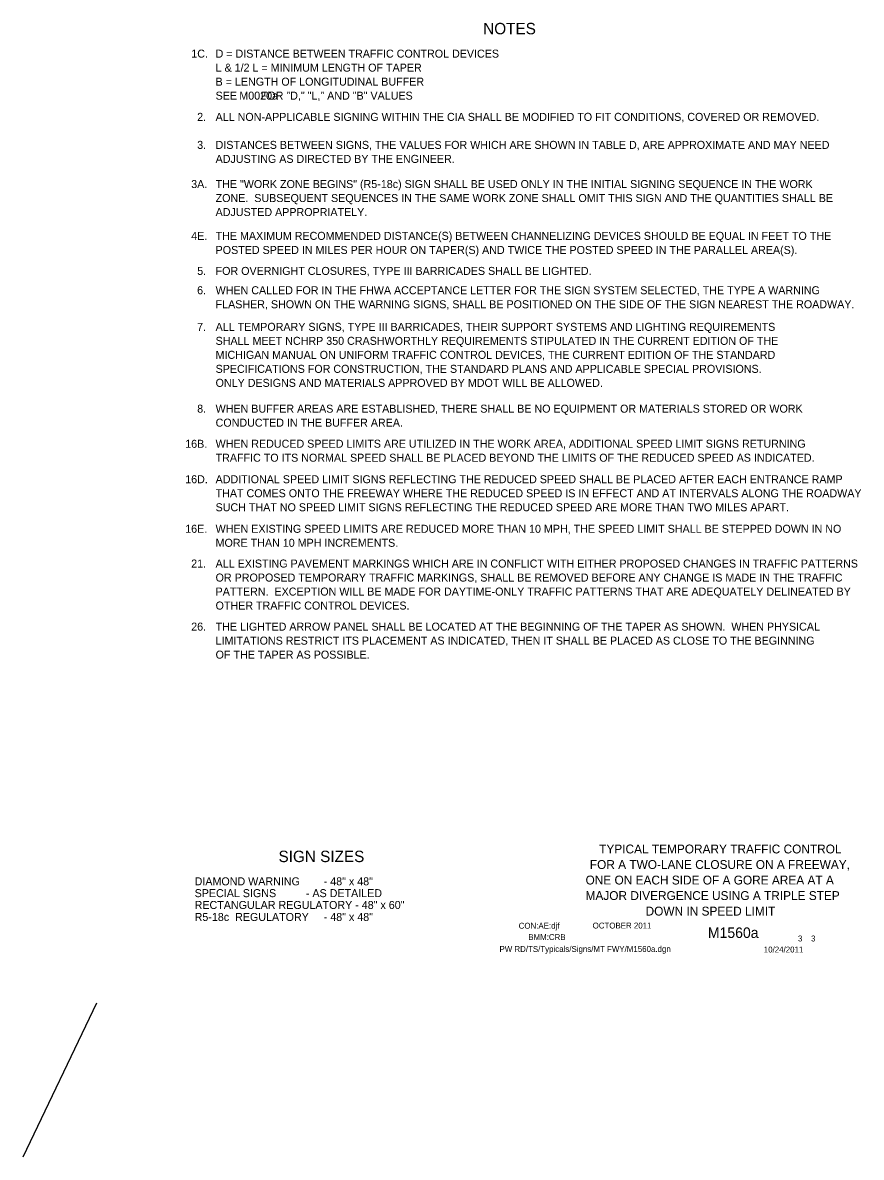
# Model space of a CAD drawing. Extents: x 16552 to 19508, y 5713 to 7079.
# Drawn here: x 18628 to 19508, y 5718 to 6909 of the extents above; entities that cross this region are included whole.
import ezdxf

# ---------------------------------------------------------------- set-up
doc = ezdxf.new("R2010")
doc.units = 0
for name, color, linetype in [('BORDER', 7, 'Continuous'), ('BORDER_SIGNAL_WO', 7, 'Continuous'), ('TYPICAL_TEXT_DIMEN_PR', 7, 'Continuous')]:
    doc.layers.add(name, color=color, linetype=linetype)

msp = doc.modelspace()

# ---------------------------------------------------------------- linework, layer by layer
at = {"layer": 'TYPICAL_TEXT_DIMEN_PR'}
msp.add_line((18705.8, 5880), (18628.3, 5718.1), dxfattribs=at)

# ---------------------------------------------------------------- texts
at = {"layer": 'BORDER'}
for s, p in [('TYPICAL TEMPORARY TRAFFIC CONTROL', (19233.2, 6037.1)), ('FOR A TWO-LANE CLOSURE ON A FREEWAY,', (19223.4, 6020.8)), ('ONE ON EACH SIDE OF A GORE AREA AT A ', (19218.9, 6004.5)), ('MAJOR DIVERGENCE USING A TRIPLE STEP ', (19218.9, 5988.2)), ('DOWN IN SPEED LIMIT', (19281.9, 5971.9))]:
    msp.add_text(s, height=9.3, dxfattribs=at).set_placement(p)
at = {"layer": 'BORDER_SIGNAL_WO'}
for s, height, p in [('CON:AE:djf  ', 6.2, (19148.7, 5958.1)), ('    OCTOBER 2011    ', 6.2, (19217.1, 5958.3)), ('    M1560a   ', 11, (19330.9, 5948.4)), ('BMM:CRB   ', 6.2, (19158.8, 5946.2)), (' 3    3 ', 6.2, (19439.4, 5944.7)), ('PW RD/TS/Typicals/Signs/MT FWY/M1560a.dgn      ', 6.2, (19128.6, 5933.7)), ('10/24/2011    ', 6.2, (19405.9, 5933.1))]:
    msp.add_text(s, height=height, dxfattribs=at).set_placement(p)
at = {"layer": 'TYPICAL_TEXT_DIMEN_PR'}
for s, height, p in [('NOTES', 12, (19111.5, 6897)), ('1C.', 8.4, (18805.2, 6872.5)), ('D = DISTANCE BETWEEN TRAFFIC CONTROL DEVICES', 8.4, (18830.7, 6872.5)), ('L & 1/2 L = MINIMUM LENGTH OF TAPER', 8.4, (18830.7, 6857.8)), ('B = LENGTH OF LONGITUDINAL BUFFER', 8.4, (18830.7, 6843.1)), ('SEE        FOR "D," "L," AND "B" VALUES', 8.4, (18830.7, 6828.4)), ('M0020a', 8.4, (18855.6, 6828.4)), ('2.', 8.4, (18811.4, 6806.1)), ('ALL NON-APPLICABLE SIGNING WITHIN THE CIA SHALL BE MODIFIED TO FIT CONDITIONS, COVERED OR REMOVED.', 8.4, (18830.7, 6806.1)), ('3.', 8.4, (18811.4, 6776.7)), ('DISTANCES BETWEEN SIGNS, THE VALUES FOR WHICH ARE SHOWN IN TABLE D, ARE APPROXIMATE AND MAY NEED', 8.4, (18830.7, 6776.7)), ('ADJUSTING AS DIRECTED BY THE ENGINEER.', 8.4, (18830.7, 6762)), ('3A.', 8.4, (18805.1, 6735.6)), ('THE "WORK ZONE BEGINS" (R5-18c) SIGN SHALL BE USED ONLY IN THE INITIAL SIGNING SEQUENCE IN THE WORK', 8.4, (18830.7, 6735.6)), ('ZONE.  SUBSEQUENT SEQUENCES IN THE SAME WORK ZONE SHALL OMIT THIS SIGN AND THE QUANTITIES SHALL BE', 8.4, (18830.7, 6720.9)), ('ADJUSTED APPROPRIATELY.', 8.4, (18830.7, 6706.2)), ('4E.', 8.4, (18805.1, 6681.2)), ('THE MAXIMUM RECOMMENDED DISTANCE(S) BETWEEN CHANNELIZING DEVICES SHOULD BE EQUAL IN FEET TO THE', 8.4, (18830.7, 6681.2)), ('POSTED SPEED IN MILES PER HOUR ON TAPER(S) AND TWICE THE POSTED SPEED IN THE PARALLEL AREA(S).', 8.4, (18830.7, 6666.4)), ('5.', 8.4, (18811.4, 6644.4)), ('FOR OVERNIGHT CLOSURES, TYPE III BARRICADES SHALL BE LIGHTED. ', 8.4, (18830.7, 6644.4)), ('6.', 8.4, (18811.3, 6624.1)), ('WHEN CALLED FOR IN THE FHWA ACCEPTANCE LETTER FOR THE SIGN SYSTEM SELECTED, THE TYPE A WARNING ', 8.4, (18830.7, 6624.1)), ('FLASHER, SHOWN ON THE WARNING SIGNS, SHALL BE POSITIONED ON THE SIDE OF THE SIGN NEAREST THE ROADWAY.', 8.4, (18830.7, 6609.4)), ('7.', 8.4, (18811.3, 6585.7)), ('ALL TEMPORARY SIGNS, TYPE III BARRICADES, THEIR SUPPORT SYSTEMS AND LIGHTING REQUIREMENTS', 8.4, (18830.7, 6585.7)), ('SHALL MEET NCHRP 350 CRASHWORTHLY REQUIREMENTS STIPULATED IN THE CURRENT EDITION OF THE', 8.4, (18830.7, 6571)), ('MICHIGAN MANUAL ON UNIFORM TRAFFIC CONTROL DEVICES, THE CURRENT EDITION OF THE STANDARD', 8.4, (18830.7, 6556.3)), ('SPECIFICATIONS FOR CONSTRUCTION, THE STANDARD PLANS AND APPLICABLE SPECIAL PROVISIONS.', 8.4, (18830.7, 6541.6)), ('ONLY DESIGNS AND MATERIALS APPROVED BY MDOT WILL BE ALLOWED.', 8.4, (18830.7, 6526.9)), ('8.', 8.4, (18811.4, 6499.8)), ('WHEN BUFFER AREAS ARE ESTABLISHED, THERE SHALL BE NO EQUIPMENT OR MATERIALS STORED OR WORK     ', 8.4, (18830.7, 6499.8)), ('CONDUCTED IN THE BUFFER AREA.', 8.4, (18830.7, 6485.1)), ('16B.', 8.4, (18798.8, 6462.9)), ('WHEN REDUCED SPEED LIMITS ARE UTILIZED IN THE WORK AREA, ADDITIONAL SPEED LIMIT SIGNS RETURNING', 8.4, (18830.7, 6463)), ('TRAFFIC TO ITS NORMAL SPEED SHALL BE PLACED BEYOND THE LIMITS OF THE REDUCED SPEED AS INDICATED.', 8.4, (18830.7, 6448.3)), ('16D.', 8.4, (18798.8, 6425.7)), ('ADDITIONAL SPEED LIMIT SIGNS REFLECTING THE REDUCED SPEED SHALL BE PLACED AFTER EACH ENTRANCE RAMP', 8.4, (18830.7, 6425.7)), ('THAT COMES ONTO THE FREEWAY WHERE THE REDUCED SPEED IS IN EFFECT AND AT INTERVALS ALONG THE ROADWAY', 8.4, (18830.7, 6411)), ('SUCH THAT NO SPEED LIMIT SIGNS REFLECTING THE REDUCED SPEED ARE MORE THAN TWO MILES APART.', 8.4, (18830.7, 6396.3)), ('16E.', 8.4, (18798.8, 6373.7)), ('WHEN EXISTING SPEED LIMITS ARE REDUCED MORE THAN 10 MPH, THE SPEED LIMIT SHALL BE STEPPED DOWN IN NO', 8.4, (18830.7, 6373.7)), ('MORE THAN 10 MPH INCREMENTS.', 8.4, (18830.7, 6359)), ('21.', 8.4, (18805.1, 6337.2)), ('ALL EXISTING PAVEMENT MARKINGS WHICH ARE IN CONFLICT WITH EITHER PROPOSED CHANGES IN TRAFFIC PATTERNS', 8.4, (18830.7, 6337.2)), ('OR PROPOSED TEMPORARY TRAFFIC MARKINGS, SHALL BE REMOVED BEFORE ANY CHANGE IS MADE IN THE TRAFFIC', 8.4, (18830.7, 6322.5)), ('PATTERN.  EXCEPTION WILL BE MADE FOR DAYTIME-ONLY TRAFFIC PATTERNS THAT ARE ADEQUATELY DELINEATED BY', 8.4, (18830.7, 6307.8)), ('OTHER TRAFFIC CONTROL DEVICES.', 8.4, (18830.7, 6293.1)), ('26.', 8.4, (18805.1, 6271)), ('THE LIGHTED ARROW PANEL SHALL BE LOCATED AT THE BEGINNING OF THE TAPER AS SHOWN.  WHEN PHYSICAL', 8.4, (18830.7, 6271)), ('LIMITATIONS RESTRICT ITS PLACEMENT AS INDICATED, THEN IT SHALL BE PLACED AS CLOSE TO THE BEGINNING', 8.4, (18830.7, 6256.3)), ('OF THE TAPER AS POSSIBLE.', 8.4, (18830.7, 6241.6)), ('SIGN SIZES', 12, (18896.7, 6028)), ('DIAMOND WARNING        - 48" x 48"', 8.4, (18808.7, 6003.6)), ('SPECIAL SIGNS          - AS DETAILED', 8.4, (18808.7, 5991.2)), ('RECTANGULAR REGULATORY - 48" x 60"', 8.4, (18808.7, 5978.8)), ('R5-18c  REGULATORY     - 48" x 48"', 8.4, (18808.7, 5966.2))]:
    msp.add_text(s, height=height, dxfattribs=at).set_placement(p)

doc.saveas('drawing.dxf')
